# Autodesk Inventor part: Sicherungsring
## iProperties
Shininess: 20.0
Angle Display Precision: 2
Document Length Units: 11269
Document Angle Units: 11279
Document Time Units: 11290
Document Mass Units: 11283
Document Length Units Precision: 3
Document Angle Units Precision: 2
Created: 2003-02
Part Number: Sicherungsring
Material: Stahl (hohe Festigk., niedr. Legier.)
Document SubType Name: Modellieren
Designer: Administrator
Density: 0.0
Volumn: 0.0
Area: 0.0
PropertySet Name: Model Information
Control State: 0
Master: False
Checked Out: False
Author: Administrator
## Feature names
1. Extrusion1
